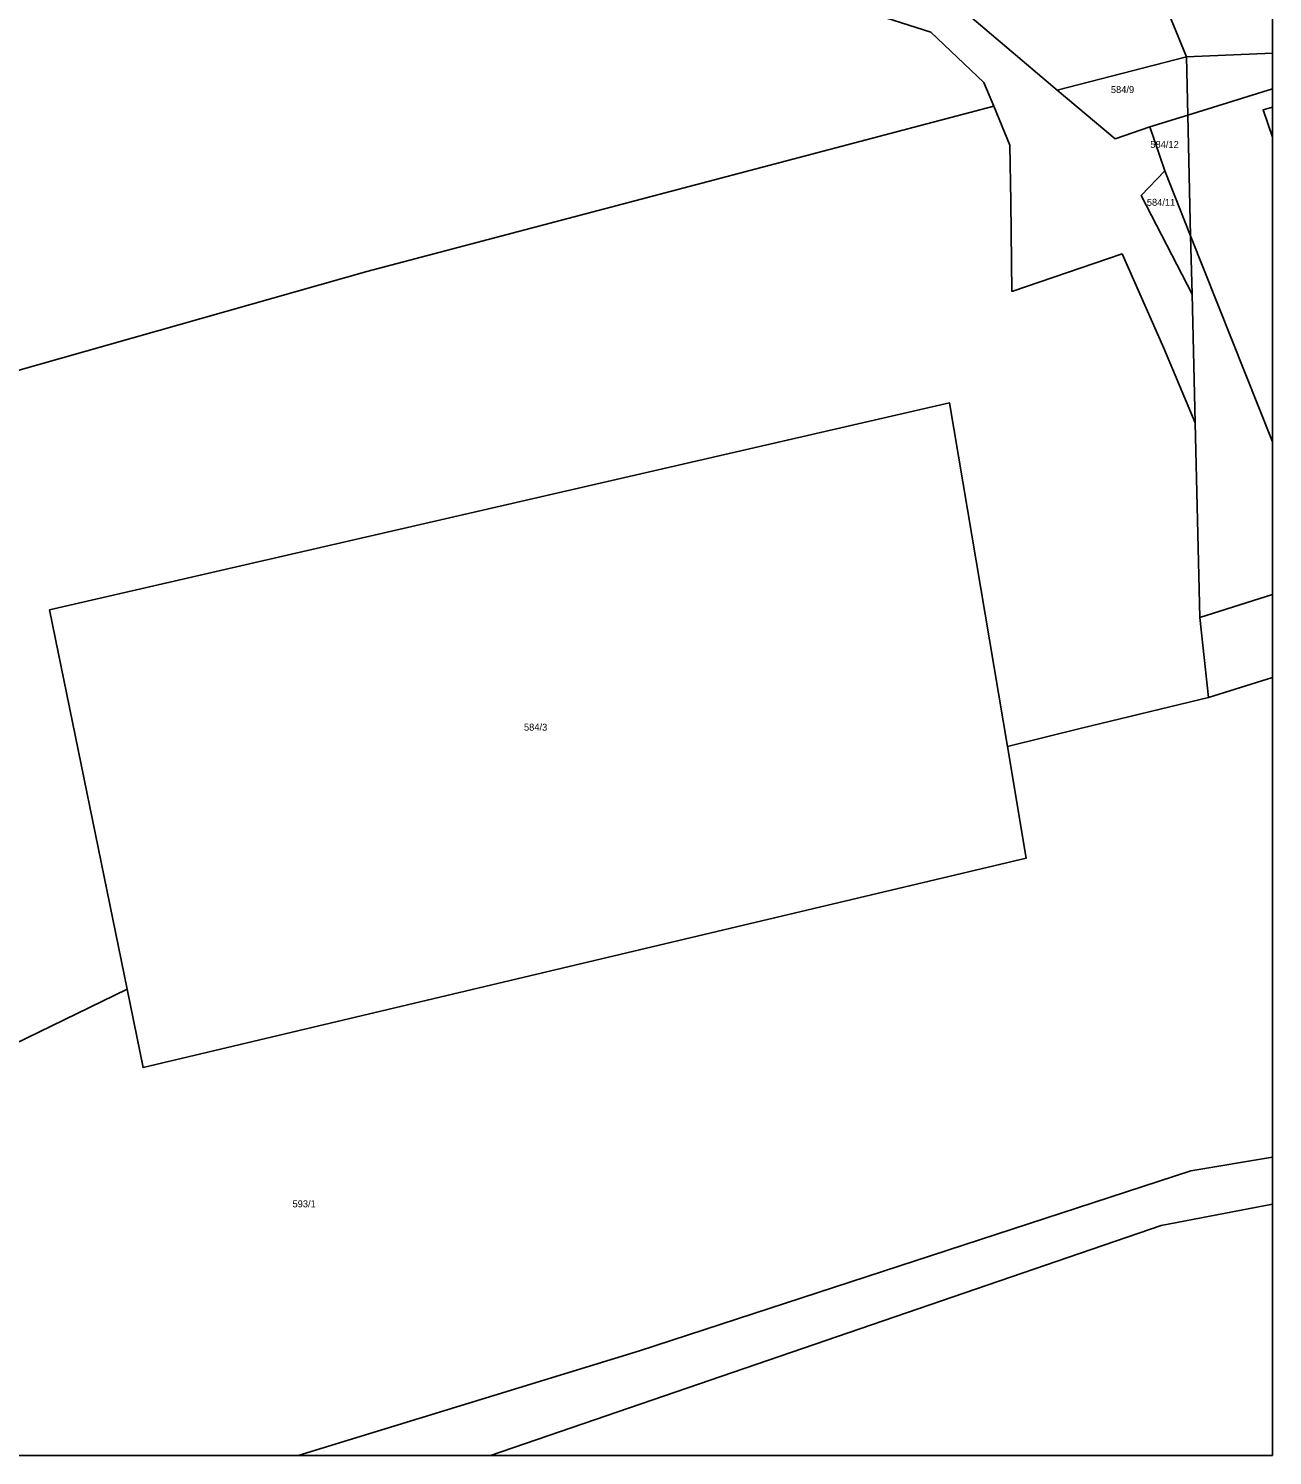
# Model space of a CAD drawing. Extents: x -873642 to -872917, y -1012962 to -1012567.
# Drawn here: x -873068.9 to -872916.9, y -1012961.7 to -1012787.3 of the extents above; entities that cross this region are included whole.
import ezdxf

# ---------------------------------------------------------------- set-up
doc = ezdxf.new("R2010")
doc.units = 0
for name, color, linetype in [('cisla_parcelni_kn', 7, 'Continuous'), ('parcely_kn', 7, 'Continuous'), ('stavebni_objekty_ostatni', 7, 'Continuous')]:
    doc.layers.add(name, color=color, linetype=linetype)

msp = doc.modelspace()

# ---------------------------------------------------------------- linework, layer by layer
at = {"layer": 'parcely_kn'}
for p, q in [((-872916.93, -1012790.31), (-872916.93, -1012637.66)), ((-872916.93, -1012790.31), (-872916.93, -1012637.66)), ((-872916.93, -1012794.66), (-872916.93, -1012790.31)), ((-872916.93, -1012794.66), (-872916.93, -1012790.31)), ((-872916.93, -1012796.89), (-872916.93, -1012794.66)), ((-872916.93, -1012796.89), (-872916.93, -1012794.66)), ((-872916.93, -1012800.58), (-872916.93, -1012796.89)), ((-872916.93, -1012800.58), (-872916.93, -1012796.89)), ((-872916.93, -1012837.8), (-872916.93, -1012800.58)), ((-872916.93, -1012837.8), (-872916.93, -1012800.58)), ((-872916.93, -1012856.47), (-872916.93, -1012837.8)), ((-872916.93, -1012856.47), (-872916.93, -1012837.8)), ((-872916.93, -1012866.59), (-872916.93, -1012856.47)), ((-872916.93, -1012866.59), (-872916.93, -1012856.47)), ((-872916.93, -1012925.25), (-872916.93, -1012866.59)), ((-872916.93, -1012925.25), (-872916.93, -1012866.59)), ((-872916.93, -1012930.97), (-872916.93, -1012925.25)), ((-872916.93, -1012930.97), (-872916.93, -1012925.25)), ((-873219.62, -1012961.69), (-873035.97, -1012961.69)), ((-873219.62, -1012961.69), (-873035.97, -1012961.69)), ((-873035.97, -1012961.69), (-873012.46, -1012961.69)), ((-873035.97, -1012961.69), (-873012.46, -1012961.69))]:
    msp.add_line(p, q, dxfattribs=at)
for points in [[(-872916.93, -1012637.66), (-872945.94, -1012694.15), (-872972.67, -1012680.42), (-872927.45, -1012790.77), (-872916.93, -1012790.31)], [(-872916.93, -1012637.66), (-872945.94, -1012694.15), (-872972.67, -1012680.42), (-872927.45, -1012790.77), (-872916.93, -1012790.31)], [(-872972.67, -1012680.42), (-872927.45, -1012790.77), (-872943.22, -1012794.81), (-872954.48, -1012785.31)], [(-872972.67, -1012680.42), (-872927.45, -1012790.77), (-872943.22, -1012794.81), (-872954.48, -1012785.31)], [(-872975.04, -1012782.47), (-872958.67, -1012787.72), (-872952.18, -1012793.89), (-872950.97, -1012796.8), (-873027.6, -1012816.97), (-873070.53, -1012829.18), (-873089.68, -1012834.35), (-873128.68, -1012843.28), (-873138.01, -1012845.62), (-873149.77, -1012848.73), (-873202.95, -1012863.9)], [(-872975.04, -1012782.47), (-872958.67, -1012787.72), (-872952.18, -1012793.89), (-872950.97, -1012796.8), (-873027.6, -1012816.97), (-873070.53, -1012829.18), (-873089.68, -1012834.35), (-873128.68, -1012843.28), (-873138.01, -1012845.62), (-873149.77, -1012848.73), (-873202.95, -1012863.9)], [(-872954.48, -1012785.31), (-872943.22, -1012794.81), (-872936.16, -1012800.77), (-872931.92, -1012799.33), (-872930.09, -1012804.69), (-872932.97, -1012807.69), (-872926.74, -1012819.75), (-872926.38, -1012835.5), (-872930.2, -1012826.37), (-872935.31, -1012814.84), (-872948.77, -1012819.42), (-872948.91, -1012808.46), (-872949, -1012801.53), (-872950.97, -1012796.8), (-872952.18, -1012793.89), (-872958.67, -1012787.72), (-872975.04, -1012782.47)], [(-872954.48, -1012785.31), (-872943.22, -1012794.81), (-872936.16, -1012800.77), (-872931.92, -1012799.33), (-872930.09, -1012804.69), (-872932.97, -1012807.69), (-872926.74, -1012819.75), (-872926.38, -1012835.5), (-872930.2, -1012826.37), (-872935.31, -1012814.84), (-872948.77, -1012819.42), (-872948.91, -1012808.46), (-872949, -1012801.53), (-872950.97, -1012796.8), (-872952.18, -1012793.89), (-872958.67, -1012787.72), (-872975.04, -1012782.47)], [(-872916.93, -1012790.31), (-872927.45, -1012790.77), (-872927.28, -1012797.88), (-872916.93, -1012794.66)], [(-872916.93, -1012790.31), (-872927.45, -1012790.77), (-872927.28, -1012797.88), (-872916.93, -1012794.66)], [(-872916.93, -1012794.66), (-872927.28, -1012797.88), (-872926.93, -1012812.65), (-872916.93, -1012837.8)], [(-872916.93, -1012794.66), (-872927.28, -1012797.88), (-872926.93, -1012812.65), (-872916.93, -1012837.8)], [(-872916.93, -1012796.89), (-872918.07, -1012797.23), (-872916.93, -1012800.58)], [(-872916.93, -1012800.58), (-872918.07, -1012797.23), (-872916.93, -1012796.89)], [(-872916.93, -1012796.89), (-872918.07, -1012797.23), (-872916.93, -1012800.58)], [(-872916.93, -1012800.58), (-872918.07, -1012797.23), (-872916.93, -1012796.89)], [(-872916.93, -1012837.8), (-872926.93, -1012812.65), (-872926.74, -1012819.75), (-872926.38, -1012835.5), (-872925.8, -1012859.29), (-872916.93, -1012856.47)], [(-872916.93, -1012837.8), (-872926.93, -1012812.65), (-872926.74, -1012819.75), (-872926.38, -1012835.5), (-872925.8, -1012859.29), (-872916.93, -1012856.47)], [(-872916.93, -1012856.47), (-872925.8, -1012859.29), (-872924.74, -1012869.07), (-872916.93, -1012866.59)], [(-872916.93, -1012856.47), (-872925.8, -1012859.29), (-872924.74, -1012869.07), (-872916.93, -1012866.59)], [(-872916.93, -1012866.59), (-872924.74, -1012869.07), (-872940.25, -1012872.81), (-872949.32, -1012875.06), (-872947.03, -1012888.69), (-873054.93, -1012914.29), (-873056.89, -1012904.69), (-873081.5, -1012916.68), (-873144.57, -1012937.76), (-873157.54, -1012937.35), (-873165.87, -1012937.08), (-873219.62, -1012961.69)], [(-872916.93, -1012866.59), (-872924.74, -1012869.07), (-872940.25, -1012872.81), (-872949.32, -1012875.06), (-872947.03, -1012888.69), (-873054.93, -1012914.29), (-873056.89, -1012904.69), (-873081.5, -1012916.68), (-873144.57, -1012937.76), (-873157.54, -1012937.35), (-873165.87, -1012937.08), (-873219.62, -1012961.69)], [(-872916.93, -1012925.25), (-872926.91, -1012926.91), (-872994.29, -1012948.9), (-873035.97, -1012961.69)], [(-873035.97, -1012961.69), (-872994.29, -1012948.9), (-872926.91, -1012926.91), (-872916.93, -1012925.25)], [(-872916.93, -1012925.25), (-872926.91, -1012926.91), (-872994.29, -1012948.9), (-873035.97, -1012961.69)], [(-873035.97, -1012961.69), (-872994.29, -1012948.9), (-872926.91, -1012926.91), (-872916.93, -1012925.25)], [(-873012.46, -1012961.69), (-872930.53, -1012933.59), (-872916.93, -1012930.97)], [(-873012.46, -1012961.69), (-872930.53, -1012933.59), (-872916.93, -1012930.97)], [(-873012.46, -1012961.69), (-872916.93, -1012961.69), (-872916.93, -1012930.97)], [(-872916.93, -1012930.97), (-872930.53, -1012933.59), (-873012.46, -1012961.69)]]:
    msp.add_lwpolyline(points, dxfattribs=at)
for points in [[(-872943.22, -1012794.81), (-872927.45, -1012790.77), (-872927.28, -1012797.88), (-872931.92, -1012799.33), (-872936.16, -1012800.77)], [(-872943.22, -1012794.81), (-872927.45, -1012790.77), (-872927.28, -1012797.88), (-872931.92, -1012799.33), (-872936.16, -1012800.77)], [(-873144.57, -1012937.76), (-873138.01, -1012845.62), (-873128.68, -1012843.28), (-873089.68, -1012834.35), (-873070.53, -1012829.18), (-873027.6, -1012816.97), (-872950.97, -1012796.8), (-872949, -1012801.53), (-872948.91, -1012808.46), (-872948.77, -1012819.42), (-872935.31, -1012814.84), (-872930.2, -1012826.37), (-872926.38, -1012835.5), (-872925.8, -1012859.29), (-872924.74, -1012869.07), (-872940.25, -1012872.81), (-872949.32, -1012875.06), (-872956.39, -1012833.05), (-873066.36, -1012858.33), (-873056.89, -1012904.69), (-873081.5, -1012916.68)], [(-873144.57, -1012937.76), (-873138.01, -1012845.62), (-873128.68, -1012843.28), (-873089.68, -1012834.35), (-873070.53, -1012829.18), (-873027.6, -1012816.97), (-872950.97, -1012796.8), (-872949, -1012801.53), (-872948.91, -1012808.46), (-872948.77, -1012819.42), (-872935.31, -1012814.84), (-872930.2, -1012826.37), (-872926.38, -1012835.5), (-872925.8, -1012859.29), (-872924.74, -1012869.07), (-872940.25, -1012872.81), (-872949.32, -1012875.06), (-872956.39, -1012833.05), (-873066.36, -1012858.33), (-873056.89, -1012904.69), (-873081.5, -1012916.68)], [(-872931.92, -1012799.33), (-872927.28, -1012797.88), (-872926.93, -1012812.65), (-872930.09, -1012804.69)], [(-872931.92, -1012799.33), (-872927.28, -1012797.88), (-872926.93, -1012812.65), (-872930.09, -1012804.69)], [(-872926.93, -1012812.65), (-872926.74, -1012819.75), (-872932.97, -1012807.69), (-872930.09, -1012804.69)], [(-872926.93, -1012812.65), (-872926.74, -1012819.75), (-872932.97, -1012807.69), (-872930.09, -1012804.69)], [(-872956.39, -1012833.05), (-872949.32, -1012875.06), (-872947.03, -1012888.69), (-873054.93, -1012914.29), (-873056.89, -1012904.69), (-873066.36, -1012858.33)], [(-872956.39, -1012833.05), (-872949.32, -1012875.06), (-872947.03, -1012888.69), (-873054.93, -1012914.29), (-873056.89, -1012904.69), (-873066.36, -1012858.33)]]:
    msp.add_lwpolyline(points, close=True, dxfattribs=at)
at = {"layer": 'stavebni_objekty_ostatni'}
msp.add_line((-872916.93, -1012800.58), (-872916.93, -1012796.89), dxfattribs=at)
msp.add_lwpolyline([(-872916.93, -1012796.89), (-872918.07, -1012797.23), (-872916.93, -1012800.58)], dxfattribs=at)

# ---------------------------------------------------------------- texts
at = {"layer": 'cisla_parcelni_kn'}
for s, p in [('584/9', (-872936.67, -1012795.18)), ('584/9', (-872936.67, -1012795.18)), ('584/12', (-872931.85, -1012801.89)), ('584/12', (-872931.85, -1012801.89)), ('584/11', (-872932.28, -1012808.96)), ('584/11', (-872932.28, -1012808.96)), ('584/3', (-873008.39, -1012873.11)), ('584/3', (-873008.39, -1012873.11)), ('593/1', (-873036.67, -1012931.36)), ('593/1', (-873036.67, -1012931.36))]:
    msp.add_text(s, height=0.85, dxfattribs=at).set_placement(p)

doc.saveas('drawing.dxf')
